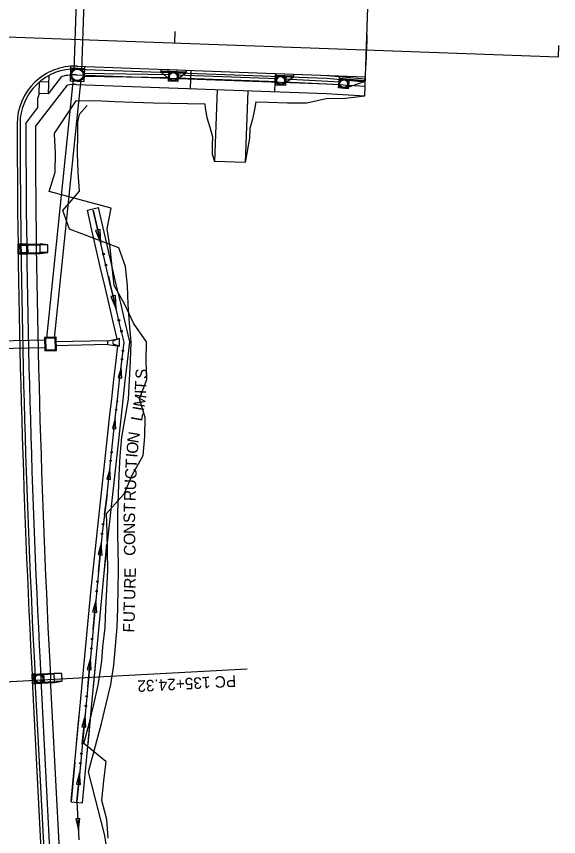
# Model space of a CAD drawing. Extents: x 979959 to 994833, y 1835619 to 1845316.
# Drawn here: x 992490.3 to 992772.8, y 1842198 to 1842625.6 of the extents above; entities that cross this region are included whole.
import ezdxf

# ---------------------------------------------------------------- set-up
doc = ezdxf.new("R2010")
doc.units = 0
for name, color, linetype in [('Future 5 Lane Construction Limits', 7, 'Continuous'), ('R_Drainage', 7, 'Continuous'), ('R_Horz Alg', 7, 'Continuous'), ('R_Horz Alg Annot', 7, 'Continuous'), ('R_Horz Alg Stationing', 7, 'Continuous'), ('R_Horz Alg Stationing_Side Road', 7, 'Continuous'), ('R_Proposed Const Limits', 7, 'Continuous'), ('R_Proposed Road', 7, 'Continuous'), ('R_Special Ditch', 7, 'Continuous')]:
    doc.layers.add(name, color=color, linetype=linetype)

msp = doc.modelspace()

# ---------------------------------------------------------------- linework, layer by layer
at = {"layer": 'Future 5 Lane Construction Limits'}
for points in [[(992527.9, 1842231.75), (992534.64, 1842257.05), (992536.97, 1842267.19), (992539.43, 1842277.33), (992541.1, 1842287.37), (992541.88, 1842297.32), (992542.82, 1842307.27), (992543.07, 1842317.18), (992543.33, 1842327.09), (992543.55, 1842336.99), (992543.49, 1842339.65), (992543.32, 1842346.88), (992543.1, 1842356.76), (992543.09, 1842366.65), (992543.45, 1842376.56), (992543.88, 1842386.46), (992544.32, 1842396.36), (992545.26, 1842406.28), (992546.88, 1842416.2), (992548.63, 1842426.13), (992549.18, 1842436.02), (992549.72, 1842445.9), (992549.99, 1842455.78), (992549.18, 1842465.63), (992548.44, 1842475.49), (992548.08, 1842485.36), (992547.08, 1842495.21), (992543.6, 1842505.04), (992517.88, 1842514.62), (992514.44, 1842524.5), (992523.23, 1842534.5), (992522.46, 1842544.41), (992522.08, 1842554.32), (992522.3, 1842564.24), (992522.33, 1842570.53), (992523.21, 1842574.73), (992527.2, 1842579.23)], [(992555.13, 1841936.67), (992544.84, 1841952.86), (992539.14, 1842056.63), (992543.41, 1842082.28), (992543.24, 1842087.29), (992542.46, 1842097.61), (992541.44, 1842107.37), (992541.12, 1842116.82), (992541.15, 1842126.86), (992540.77, 1842136.87), (992540.77, 1842146.45), (992541.26, 1842156.64), (992540.93, 1842167.72), (992539.18, 1842178.11), (992537.94, 1842187.98), (992536.34, 1842198.52), (992527.9, 1842231.75)]]:
    msp.add_lwpolyline(points, dxfattribs=at)
at = {"layer": 'R_Drainage'}
for p, q in [((992521.45, 1842633.21), (992520.14, 1842597.44)), ((992525.44, 1842633.07), (992524.13, 1842597.3)), ((992570.21, 1842595.09), (992524.97, 1842595.84)), ((992565.63, 1842596.54), (992570.42, 1842592.41)), ((992578.64, 1842596.56), (992565.64, 1842597.04)), ((992578.62, 1842596.07), (992573.54, 1842592.3)), ((992519.84, 1842593.11), (992505.96, 1842457.81)), ((992523.82, 1842592.71), (992509.99, 1842457.9)), ((992570.18, 1842593.59), (992524.95, 1842594.34)), ((992574.46, 1842591.71), (992569.46, 1842591.9)), ((992626.14, 1842591.57), (992573.87, 1842593.49)), ((992626.19, 1842593.07), (992573.93, 1842594.99)), ((992634.6, 1842594.51), (992625.61, 1842594.84)), ((992634.58, 1842594.02), (992629.51, 1842590.25)), ((992658.97, 1842589.89), (992629.83, 1842591.41)), ((992659.05, 1842591.39), (992629.91, 1842592.91)), ((992671.55, 1842592.06), (992658.6, 1842593.27)), ((992671.5, 1842591.56), (992661.67, 1842588.18)), ((992630.42, 1842589.66), (992625.43, 1842589.85)), ((992663.12, 1842587.82), (992658.14, 1842588.29)), ((992527.28, 1842524.63), (992533.13, 1842525.95)), ((992492.63, 1842506.86), (992491.13, 1842506.84)), ((992492.13, 1842506.85), (992502.63, 1842506.99)), ((992492.2, 1842501.85), (992492.13, 1842506.85)), ((992492.64, 1842506.36), (992502.64, 1842506.49)), ((992492.69, 1842502.36), (992492.64, 1842506.36)), ((992506.64, 1842506.54), (992502.63, 1842506.99)), ((992506.64, 1842506.54), (992502.64, 1842506.49)), ((992502.69, 1842502.49), (992502.64, 1842506.49)), ((992506.69, 1842502.54), (992506.64, 1842506.54)), ((992492.2, 1842501.85), (992502.69, 1842501.99)), ((992492.69, 1842502.36), (992502.69, 1842502.49)), ((992502.69, 1842501.99), (992506.69, 1842502.54)), ((992506.69, 1842502.54), (992502.69, 1842502.49)), ((992505.5, 1842456.8), (992443.02, 1842455.42)), ((992537.9, 1842456.52), (992510.52, 1842455.91)), ((992537.94, 1842454.52), (992510.57, 1842453.91)), ((992537.9, 1842456.52), (992544, 1842457.65)), ((992537.94, 1842454.52), (992537.9, 1842456.52)), ((992537.94, 1842454.52), (992544.08, 1842453.65)), ((992544, 1842457.65), (992541.22, 1842456.7)), ((992544.08, 1842453.65), (992541.26, 1842454.48)), ((992544.08, 1842453.65), (992544, 1842457.65)), ((992505.59, 1842452.8), (992443.11, 1842451.42)), ((992535.97, 1842335.33), (992537.4, 1842350.6)), ((992518.81, 1842216.39), (992529.18, 1842327.09)), ((992530.4, 1842275.85), (992531.8, 1842290.79)), ((992499.43, 1842282.73), (992509.92, 1842283.29)), ((992504.43, 1842283), (992504.69, 1842278)), ((992513.94, 1842283), (992509.92, 1842283.29)), ((992513.94, 1842283), (992509.95, 1842282.79)), ((992514.15, 1842279.01), (992513.94, 1842283)), ((992499.93, 1842282.76), (992498.44, 1842282.68)), ((992499.7, 1842277.74), (992499.43, 1842282.73)), ((992499.96, 1842282.26), (992509.95, 1842282.79)), ((992500.17, 1842278.27), (992499.96, 1842282.26)), ((992500.17, 1842278.27), (992510.16, 1842278.79)), ((992510.16, 1842278.79), (992509.95, 1842282.79)), ((992514.15, 1842279.01), (992510.16, 1842278.79)), ((992510.18, 1842278.29), (992514.15, 1842279.01)), ((992499.7, 1842277.74), (992510.18, 1842278.29)), ((992521.63, 1842246.51), (992523.03, 1842261.44)), ((992527.6, 1842245.95), (992529, 1842260.88)), ((992518.79, 1842216.16), (992524.76, 1842215.6))]:
    msp.add_line(p, q, dxfattribs=at)
for points in [[(992525.66, 1842598), (992518.67, 1842598.26), (992518.72, 1842599.76), (992525.72, 1842599.5)], [(992525.42, 1842591.51), (992518.43, 1842591.77), (992518.68, 1842598.76), (992525.68, 1842598.5)], [(992578.62, 1842596.07), (992565.63, 1842596.54), (992565.68, 1842598.04), (992578.67, 1842597.56)], [(992574.46, 1842591.71), (992569.46, 1842591.9), (992569.64, 1842596.89), (992574.64, 1842596.71)], [(992634.58, 1842594.02), (992625.59, 1842594.34), (992625.65, 1842595.84), (992634.64, 1842595.51)], [(992630.42, 1842589.66), (992625.43, 1842589.85), (992625.61, 1842594.84), (992630.61, 1842594.66)], [(992663.12, 1842587.82), (992658.14, 1842588.29), (992658.6, 1842593.27), (992663.58, 1842592.8)], [(992671.5, 1842591.56), (992658.56, 1842592.77), (992658.7, 1842594.26), (992671.64, 1842593.05)], [(992492.64, 1842506.86), (992492.7, 1842501.86), (992491.2, 1842501.84), (992491.14, 1842506.84)], [(992496.14, 1842506.9), (992496.19, 1842501.9), (992492.2, 1842501.85), (992492.14, 1842506.85)], [(992496.19, 1842501.9), (992496.14, 1842506.9), (992492.14, 1842506.85), (992492.2, 1842501.85)], [(992495.64, 1842506.39), (992495.69, 1842502.39), (992492.69, 1842502.36), (992492.64, 1842506.36)], [(992495.69, 1842502.39), (992495.64, 1842506.39), (992492.64, 1842506.36), (992492.69, 1842502.36)], [(992505.12, 1842451.29), (992511.12, 1842451.43), (992510.97, 1842458.42), (992504.97, 1842458.29)], [(992505.61, 1842451.8), (992510.61, 1842451.91), (992510.48, 1842457.91), (992505.48, 1842457.8)], [(992504.43, 1842283), (992504.69, 1842278), (992499.7, 1842277.74), (992499.43, 1842282.73)], [(992499.93, 1842282.76), (992500.2, 1842277.77), (992498.7, 1842277.69), (992498.44, 1842282.68)]]:
    msp.add_lwpolyline(points, close=True, dxfattribs=at)
for points in [[(992542.85, 1842457.44), (992541.09, 1842464.84), (992538.77, 1842474.68), (992536.47, 1842484.53), (992534.18, 1842494.38), (992531.91, 1842504.25), (992529.66, 1842514.12), (992527.28, 1842524.63)], [(992535.97, 1842335.33), (992544.8, 1842415.73), (992545.91, 1842425.64), (992547.03, 1842435.55), (992548.17, 1842445.45), (992549.39, 1842455.88), (992546.93, 1842466.22), (992544.61, 1842476.05), (992542.31, 1842485.89), (992540.03, 1842495.74), (992537.76, 1842505.59), (992535.51, 1842515.45), (992533.13, 1842525.95)], [(992491.13, 1842506.84), (992491.2, 1842501.84), (992492.7, 1842501.86), (992492.63, 1842506.86)], [(992529.18, 1842327.09), (992537.75, 1842406.46), (992538.84, 1842416.39), (992539.94, 1842426.31), (992541.07, 1842436.23), (992542.21, 1842446.14), (992543.11, 1842453.79)], [(992524.76, 1842215.6), (992535.97, 1842335.33)], [(992498.44, 1842282.68), (992498.7, 1842277.69), (992500.2, 1842277.77), (992499.93, 1842282.76)], [(992520.71, 1842236.73), (992518.79, 1842216.16)]]:
    msp.add_lwpolyline(points, dxfattribs=at)
for centre, radius in [((992522.05, 1842595.13), 3.5), ((992522.05, 1842595.13), 3.5), ((992522.05, 1842595.13), 3), ((992522.05, 1842595.13), 3), ((992572.05, 1842594.3), 2.5), ((992572.05, 1842594.3), 2.5), ((992572.05, 1842594.3), 2), ((992572.05, 1842594.3), 2), ((992628.02, 1842592.25), 2.5), ((992628.02, 1842592.25), 2.5), ((992628.02, 1842592.25), 2), ((992628.02, 1842592.25), 2), ((992660.86, 1842590.54), 2.5), ((992660.86, 1842590.54), 2.5), ((992660.86, 1842590.54), 2), ((992660.86, 1842590.54), 2), ((992502.06, 1842280.37), 2.5), ((992502.06, 1842280.37), 2.5), ((992502.06, 1842280.37), 2), ((992502.06, 1842280.37), 2)]:
    msp.add_circle(centre, radius, dxfattribs=at)
msp.add_arc((992541.59, 1842455.6), 1.17, 108.7959, 253.736, dxfattribs=at)
at = {"layer": 'R_Horz Alg'}
msp.add_line((992472.76, 1842615.45), (992772.56, 1842604.47), dxfattribs=at)
at = {"layer": 'R_Horz Alg Annot'}
msp.add_lwpolyline([(992480.63, 1842278.55), (992610.45, 1842285.41)], dxfattribs=at)
at = {"layer": 'R_Horz Alg Stationing'}
msp.add_lwpolyline([(992672.92, 1842616.13), (992672.33, 1842600.14)], dxfattribs=at)
at = {"layer": 'R_Horz Alg Stationing_Side Road'}
for points in [[(992572.91, 1842617.79), (992572.69, 1842611.79)], [(992672.85, 1842614.13), (992672.63, 1842608.13)], [(992772.78, 1842610.47), (992772.56, 1842604.47)]]:
    msp.add_lwpolyline(points, dxfattribs=at)
at = {"layer": 'R_Proposed Const Limits'}
msp.add_line((992521.3, 1842581.62), (992510.12, 1842564.84), dxfattribs=at)
for points in [[(992615.03, 1842581.08), (992621.6, 1842580.89), (992631.59, 1842580.52), (992641.6, 1842580.5), (992651.68, 1842582.74), (992661.7, 1842582.96), (992671.75, 1842584.2)], [(992521.3, 1842581.62), (992521.56, 1842581.64), (992531.57, 1842581.76), (992541.56, 1842581.31), (992551.55, 1842580.94), (992561.54, 1842580.54), (992588.46, 1842580.06)], [(992588.46, 1842580.06), (992588.6, 1842577.96), (992589.55, 1842572.92), (992590.98, 1842567.87), (992592.38, 1842562.81), (992592.25, 1842558.52), (992592.25, 1842553.71), (992593.45, 1842549.99)], [(992615.03, 1842581.08), (992614.32, 1842577.02), (992613.37, 1842572.05), (992611.91, 1842567.1), (992611.67, 1842562.05), (992609.44, 1842549.41)], [(992507.27, 1842534.37), (992510.49, 1842544.33), (992510.57, 1842554.27), (992510.14, 1842564.2), (992510.12, 1842564.84)], [(992537.3, 1842366.43), (992546.43, 1842376.66), (992550.83, 1842386.7), (992556.26, 1842396.75), (992557.25, 1842406.65), (992557.32, 1842416.51), (992554.34, 1842426.29), (992558.28, 1842436.25), (992557.97, 1842446.1), (992558.08, 1842455.96), (992551.35, 1842465.68), (992546.81, 1842475.46), (992541.29, 1842485.24), (992540.21, 1842495.11), (992539.05, 1842504.98), (992537.61, 1842514.84), (992539.71, 1842525.6), (992507.27, 1842534.37)], [(992536.8, 1842237.14), (992525.41, 1842246.55), (992528.23, 1842256.71), (992530.54, 1842266.85), (992532.86, 1842276.99), (992534.52, 1842287.03), (992534.71, 1842289.43), (992535.31, 1842296.99), (992536.47, 1842306.96), (992536.95, 1842316.89), (992537.4, 1842326.82), (992537.9, 1842336.75), (992537.68, 1842346.64), (992537.51, 1842356.54), (992537.3, 1842366.43)], [(992536.8, 1842237.14), (992535.71, 1842227.07), (992534.62, 1842216.99), (992537.19, 1842207.12), (992537.88, 1842197.14)]]:
    msp.add_lwpolyline(points, dxfattribs=at)
at = {"layer": 'R_Proposed Road'}
for p, q in [((992671.75, 1842584.2), (992673.63, 1842635.61)), ((992521.76, 1842599.65), (992672.11, 1842594.14)), ((992521.6, 1842595.15), (992651.96, 1842590.38)), ((992521.71, 1842598.15), (992652.07, 1842593.37)), ((992581.18, 1842597.47), (992580.83, 1842587.98)), ((992625.15, 1842595.86), (992624.8, 1842586.37)), ((992502.07, 1842585.45), (992502.29, 1842591.45)), ((992507.28, 1842591.27), (992502.29, 1842591.45)), ((992507.06, 1842585.27), (992507.42, 1842594.9)), ((992507.06, 1842585.27), (992514.02, 1842594.29)), ((992652.07, 1842593.37), (992672.02, 1842591.51)), ((992652.13, 1842594.87), (992672.07, 1842593.01)), ((992500.17, 1842568.14), (992516.88, 1842589.82)), ((992521.42, 1842590.15), (992651.78, 1842585.38)), ((992594.82, 1842587.47), (992593.45, 1842549.99)), ((992610.81, 1842586.88), (992609.44, 1842549.41)), ((992651.96, 1842590.38), (992671.93, 1842589.2)), ((992502.07, 1842585.45), (992501.52, 1842583.08)), ((992501.52, 1842578.08), (992501.52, 1842583.08)), ((992507.06, 1842585.27), (992502.07, 1842585.45)), ((992651.78, 1842585.38), (992671.75, 1842584.2)), ((992495.17, 1842569.84), (992501.52, 1842578.08)), ((992609.44, 1842549.41), (992593.45, 1842549.99)), ((992526.92, 1841743.17), (992498.6, 1842279.5)), ((992528.42, 1841743.25), (992500.1, 1842279.58)), ((992531.42, 1841743.41), (992503.1, 1842279.74)), ((992536.41, 1841743.67), (992508.09, 1842280))]:
    msp.add_line(p, q, dxfattribs=at)
for centre, radius, start, end in [((992520.67, 1842569.67), 30, 87.9024, 180.1112), ((992520.67, 1842569.67), 28.5, 87.9024, 180.1112), ((992520.67, 1842569.67), 25.5, 87.9024, 105.1165), ((992520.67, 1842569.67), 20.5, 87.9024, 100.6335), ((998202.23, 1842580.69), 5711.58, 180.11115, 183.02281), ((998202.23, 1842580.69), 5710.08, 180.11115, 183.02281), ((992520.67, 1842569.67), 25.5, 179.6047, 180.1112), ((998202.23, 1842580.69), 5707.08, 180.11115, 183.02281), ((998202.23, 1842580.69), 5702.08, 180.12608, 183.02281)]:
    msp.add_arc(centre, radius, start, end, dxfattribs=at)
at = {"layer": 'R_Special Ditch'}
for p, q in [((992533.91, 1842514.59), (992531.47, 1842514.04)), ((992531.47, 1842514.04), (992534.26, 1842507.42)), ((992534.26, 1842507.42), (992533.91, 1842514.59)), ((992541.86, 1842480.11), (992539.43, 1842479.54)), ((992542.26, 1842472.94), (992541.86, 1842480.11)), ((992539.43, 1842479.54), (992542.26, 1842472.94)), ((992544.81, 1842442.47), (992543.27, 1842437.29)), ((992545.13, 1842437.08), (992544.81, 1842442.47)), ((992543.27, 1842437.29), (992545.13, 1842437.08)), ((992541.82, 1842416.02), (992540.3, 1842410.84)), ((992542.17, 1842410.64), (992541.82, 1842416.02)), ((992540.3, 1842410.84), (992542.17, 1842410.64)), ((992538.95, 1842389.56), (992537.46, 1842384.38)), ((992539.32, 1842384.18), (992538.95, 1842389.56)), ((992537.46, 1842384.38), (992539.32, 1842384.18)), ((992534.42, 1842350.88), (992532.8, 1842345.01)), ((992534.91, 1842344.81), (992534.42, 1842350.88)), ((992532.8, 1842345.01), (992534.91, 1842344.81)), ((992531.62, 1842320.97), (992530, 1842315.1)), ((992532.11, 1842314.9), (992531.62, 1842320.97)), ((992530, 1842315.1), (992532.11, 1842314.9)), ((992528.82, 1842291.07), (992527.2, 1842285.19)), ((992529.31, 1842285), (992528.82, 1842291.07)), ((992527.2, 1842285.19), (992529.31, 1842285)), ((992526.02, 1842261.16), (992524.4, 1842255.29)), ((992526.51, 1842255.09), (992526.02, 1842261.16)), ((992524.4, 1842255.29), (992526.51, 1842255.09)), ((992523.22, 1842231.25), (992521.6, 1842225.38)), ((992523.71, 1842225.18), (992523.22, 1842231.25)), ((992521.6, 1842225.38), (992523.71, 1842225.18)), ((992523.31, 1842207.38), (992521.2, 1842207.28)), ((992521.2, 1842207.28), (992522.55, 1842201.34)), ((992522.55, 1842201.34), (992523.31, 1842207.38))]:
    msp.add_line(p, q, dxfattribs=at)
for points in [[(992546.35, 1842455.7), (992544.01, 1842465.53), (992541.69, 1842475.37), (992539.39, 1842485.21), (992537.1, 1842495.06), (992534.83, 1842504.92), (992532.58, 1842514.79), (992530.35, 1842524.66), (992530.35, 1842524.66)], [(992530.35, 1842524.66), (992532.58, 1842514.79), (992534.26, 1842507.42)], [(992538.23, 1842490.2), (992538.24, 1842490.16)], [(992538.24, 1842490.16), (992539.39, 1842485.21), (992541.69, 1842475.37), (992542.26, 1842472.94)], [(992537.57, 1842376.34), (992538.6, 1842386.28), (992539.66, 1842396.21), (992540.73, 1842406.14), (992541.82, 1842416.06), (992542.93, 1842425.97), (992544.05, 1842435.89), (992545.19, 1842445.8), (992546.35, 1842455.7)], [(992546.34, 1842455.74), (992546.35, 1842455.7)], [(992546.35, 1842455.67), (992546.35, 1842455.7)], [(992543.3, 1842429.26), (992544.05, 1842435.89), (992544.81, 1842442.47)], [(992543.3, 1842429.23), (992543.3, 1842429.26)], [(992540.37, 1842402.81), (992540.73, 1842406.14), (992541.82, 1842416.02)], [(992540.37, 1842402.78), (992540.37, 1842402.81)], [(992537.57, 1842376.34), (992538.6, 1842386.28), (992538.95, 1842389.56)], [(992537.57, 1842376.34), (992534.94, 1842356.44), (992522.76, 1842226.38), (992521.82, 1842216.32)], [(992536.18, 1842365.81), (992537.57, 1842376.34)], [(992536.17, 1842365.78), (992536.18, 1842365.81)], [(992533.02, 1842335.95), (992534.42, 1842350.88)], [(992533.01, 1842335.91), (992533.02, 1842335.95)], [(992530.22, 1842306.04), (992531.62, 1842320.97)], [(992530.21, 1842306), (992530.22, 1842306.04)], [(992527.42, 1842276.13), (992528.82, 1842291.07)], [(992527.41, 1842276.1), (992527.42, 1842276.13)], [(992524.62, 1842246.23), (992526.02, 1842261.16)], [(992524.61, 1842246.19), (992524.62, 1842246.23)], [(992521.82, 1842216.32), (992522.76, 1842226.38), (992523.22, 1842231.25)], [(992521.82, 1842216.32), (992522.3, 1842206.33), (992522.79, 1842196.34)], [(992521.82, 1842216.32), (992522.3, 1842206.33), (992522.55, 1842201.34)]]:
    msp.add_lwpolyline(points, dxfattribs=at)
for centre, radius in [((992535.62, 1842501.68), 0.442), ((992536.95, 1842495.93), 0.442), ((992543.66, 1842467.21), 0.442), ((992545.02, 1842461.47), 0.442), ((992545.8, 1842451.29), 0.332), ((992545.29, 1842446.88), 0.332), ((992542.77, 1842424.84), 0.332), ((992542.28, 1842420.43), 0.332), ((992539.86, 1842398.39), 0.332), ((992539.39, 1842393.98), 0.332), ((992535.48, 1842360.84), 0.375), ((992534.85, 1842355.87), 0.375), ((992532.51, 1842330.95), 0.375), ((992532.05, 1842325.96), 0.375), ((992529.71, 1842301.04), 0.375), ((992529.25, 1842296.06), 0.375), ((992526.91, 1842271.14), 0.375), ((992526.45, 1842266.15), 0.375), ((992524.11, 1842241.23), 0.375), ((992523.65, 1842236.24), 0.375)]:
    msp.add_circle(centre, radius, dxfattribs=at)

# ---------------------------------------------------------------- texts
at = {"layer": 'Future 5 Lane Construction Limits'}
for s, rotation, p in [('S', 86.8969, (992558.22, 1842436.45)), ('T', 86.8015, (992557.89, 1842430.59)), ('M', 79.9942, (992556.96, 1842421.53)), ('I', 86.8015, (992557.78, 1842428.61)), ('I', 79.9942, (992556.61, 1842419.58)), ('L', 79.9942, (992555.68, 1842414.27)), ('N', 80.7176, (992553.81, 1842402.83)), ('O', 84.6268, (992553.46, 1842397.39)), ('T', 87.4598, (992553.04, 1842389.85)), ('I', 84.6268, (992553.27, 1842395.41)), ('C', 87.4598, (992552.79, 1842384.19)), ('U', 87.5104, (992552.54, 1842378.44)), ('R', 87.9015, (992552.32, 1842372.81)), ('T', 87.9015, (992552.11, 1842366.96)), ('S', 90.0646, (992552.1, 1842361.52)), ('N', 90.0646, (992552.1, 1842355.85)), ('O', 91.2777, (992552.25, 1842350.12)), ('C', 91.2777, (992552.38, 1842344.45)), ('E', 88.6841, (992552.46, 1842332.79)), ('R', 88.6841, (992552.33, 1842327.13)), ('U', 88.5367, (992552.18, 1842321.35)), ('T', 88.5367, (992552.03, 1842315.49)), ('U', 88.5564, (992551.89, 1842309.73)), ('F', 88.5564, (992551.75, 1842304.35))]:
    msp.add_text(s, height=6, rotation=rotation, dxfattribs=at).set_placement(p)
at = {"layer": 'R_Horz Alg Annot'}
msp.add_text('PC 135+24.32', height=6, rotation=183.0228, dxfattribs=at).set_placement((992604.61, 1842282.09))

doc.saveas('drawing.dxf')
